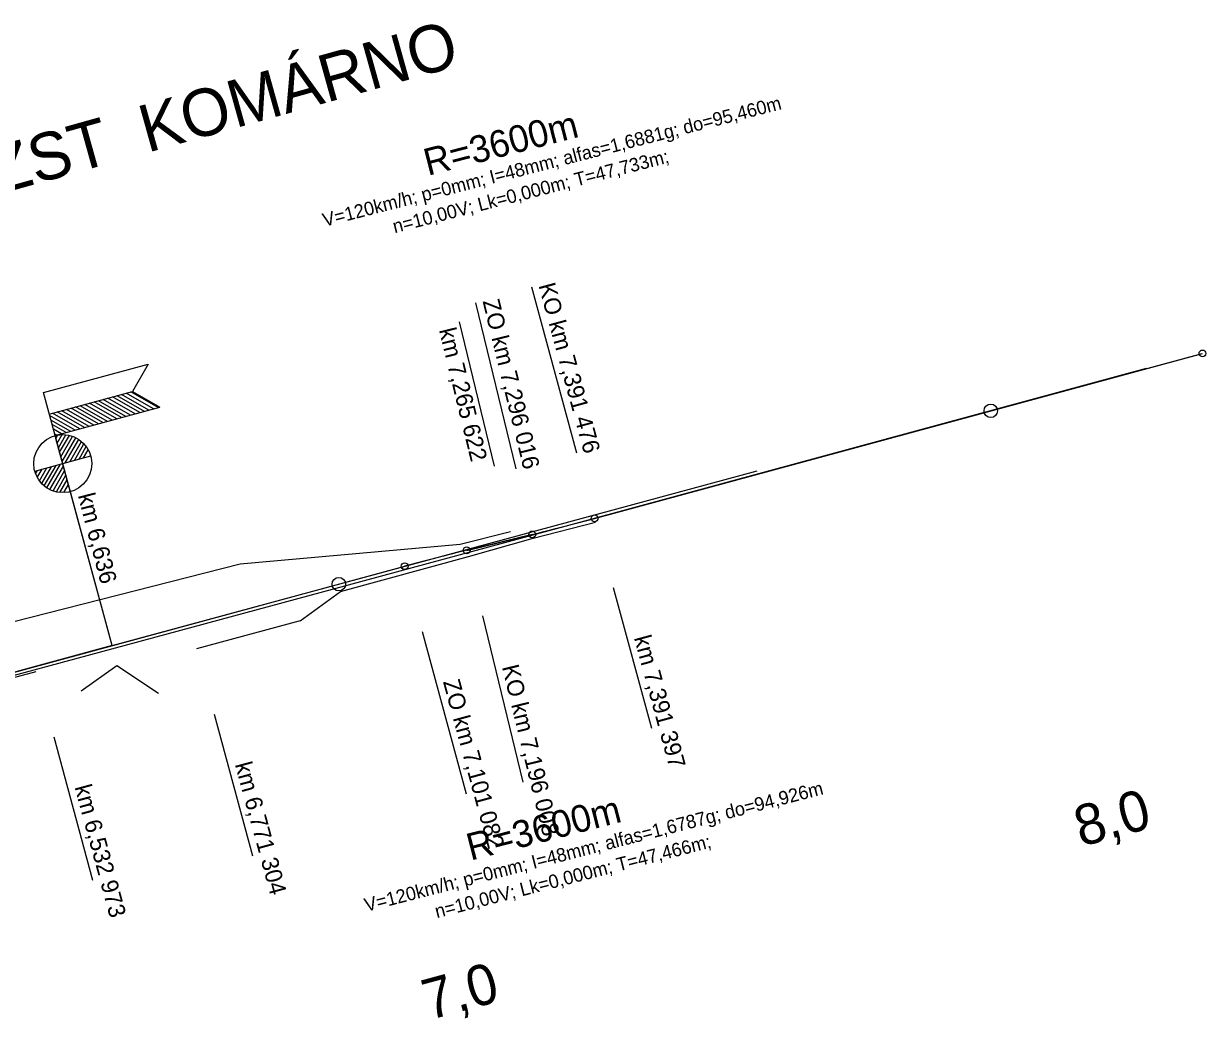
# Model space of a CAD drawing. Extents: x -504999 to -493096, y -1330712 to -1305226.
# Drawn here: x -502082 to -500334, y -1330024 to -1328550 of the extents above; entities that cross this region are included whole.
import ezdxf

# ---------------------------------------------------------------- set-up
doc = ezdxf.new("R2010")
doc.units = 0
for name, color, linetype in [('0_HM', 7, 'Continuous'), ('0_obluky', 7, 'Continuous'), ('0_popis oblukov', 7, 'Continuous'), ('0_STANICE', 7, 'Continuous'), ('0_stanicenie oblukov', 7, 'Continuous'), ('dotyčnice', 7, 'Continuous'), ('Level 1', 7, 'Continuous'), ('PHS', 7, 'Continuous')]:
    doc.layers.add(name, color=color, linetype=linetype)

msp = doc.modelspace()

# ---------------------------------------------------------------- linework, layer by layer
at = {"layer": '0_HM'}
for centre in [(-500648.1, -1329123.6), (-501614.5, -1329380.4)]:
    msp.add_circle(centre, 10, dxfattribs=at)
at = {"layer": '0_obluky'}
for p, q in [((-501235.4, -1329282.9), (-500334.3, -1329038.5)), ((-501327.8, -1329306.7), (-501425, -1329330.3)), ((-501425, -1329330.3), (-501327.8, -1329306.7)), ((-502264, -1329556.4), (-501516.9, -1329353.9))]:
    msp.add_line(p, q, dxfattribs=at)
for centre in [(-500334.3, -1329038.5), (-501235.4, -1329282.9), (-501327.8, -1329306.7), (-501425, -1329330.3), (-501516.9, -1329353.9)]:
    msp.add_circle(centre, 5, dxfattribs=at)
for centre, start, end in [((-502177.8, -1325808.5), 283.6563, 285.1756), ((-500575.1, -1332828.5), 103.6563, 105.1671)]:
    msp.add_arc(centre, 3600, start, end, dxfattribs=at)
at = {"layer": '0_STANICE'}
for p, q in [((-502052.3, -1329096.6), (-501897.3, -1329054.5)), ((-501897.3, -1329054.5), (-501920.5, -1329095)), ((-501950.7, -1329471.5), (-502052.3, -1329096.6)), ((-502043.7, -1329128.4), (-501920.5, -1329095)), ((-501936.9, -1329133.7), (-501977.4, -1329110.4)), ((-501930.1, -1329131.8), (-501970.6, -1329108.6)), ((-501923.3, -1329130), (-501963.8, -1329106.7)), ((-501916.4, -1329128.1), (-501956.9, -1329104.9)), ((-501909.6, -1329126.3), (-501950.1, -1329103)), ((-501902.8, -1329124.4), (-501943.3, -1329101.2)), ((-501896, -1329122.6), (-501936.5, -1329099.3)), ((-501889.1, -1329120.7), (-501929.6, -1329097.5)), ((-501882.3, -1329118.9), (-501922.8, -1329095.6)), ((-501920.5, -1329095), (-501880, -1329118.2)), ((-501998.3, -1329150.3), (-502038.8, -1329127.1)), ((-502035.1, -1329160.3), (-501880, -1329118.2)), ((-501991.5, -1329148.5), (-502032, -1329125.3)), ((-501984.7, -1329146.6), (-502025.2, -1329123.4)), ((-501977.9, -1329144.8), (-502018.4, -1329121.5)), ((-501971, -1329142.9), (-502011.5, -1329119.7)), ((-501964.2, -1329141.1), (-502004.7, -1329117.8)), ((-501957.4, -1329139.2), (-501997.9, -1329116)), ((-501950.6, -1329137.4), (-501991.1, -1329114.1)), ((-501943.7, -1329135.5), (-501984.2, -1329112.3)), ((-502005.2, -1329152.2), (-502043.2, -1329130.4)), ((-502012, -1329154), (-502041.3, -1329137.2)), ((-502018.8, -1329155.9), (-502039.5, -1329144)), ((-502018.8, -1329155.9), (-502039.5, -1329144)), ((-502025.6, -1329157.7), (-502037.6, -1329150.9)), ((-502025.6, -1329157.7), (-502037.6, -1329150.9)), ((-502032.5, -1329159.6), (-502035.8, -1329157.7)), ((-502033.9, -1329164.5), (-502031, -1329159.4)), ((-502032.1, -1329171.3), (-502024.9, -1329158.8)), ((-502030.2, -1329178.2), (-502019.2, -1329159)), ((-502028.4, -1329185), (-502014, -1329159.9)), ((-502026.5, -1329191.8), (-502009.1, -1329161.4)), ((-502024.7, -1329198.6), (-502004.4, -1329163.4)), ((-501950.7, -1329471.5), (-502033.9, -1329164.5)), ((-502020.1, -1329200.8), (-502000.1, -1329165.9)), ((-502013.3, -1329199), (-501996.1, -1329168.9)), ((-502006.5, -1329197.1), (-501992.4, -1329172.4)), ((-501999.7, -1329195.3), (-501989, -1329176.6)), ((-502065.3, -1329213.1), (-501982.3, -1329190.5)), ((-501992.8, -1329193.4), (-501985.9, -1329181.4)), ((-502064, -1329217), (-502061.1, -1329211.9)), ((-502061.5, -1329222.6), (-502054.3, -1329210.1)), ((-502058.4, -1329227.3), (-502047.4, -1329208.2)), ((-502055, -1329231.4), (-502040.6, -1329206.4)), ((-502051.2, -1329234.9), (-502033.8, -1329204.5)), ((-502047.2, -1329237.9), (-502027, -1329202.7)), ((-502042.8, -1329240.4), (-502022.8, -1329205.5)), ((-502038.2, -1329242.3), (-502021, -1329212.3)), ((-502033.3, -1329243.8), (-502019.1, -1329219.1)), ((-502028, -1329244.6), (-502017.3, -1329225.9)), ((-502022.3, -1329244.8), (-502015.4, -1329232.8))]:
    msp.add_line(p, q, dxfattribs=at)
msp.add_circle((-502023.8, -1329201.8), 43, dxfattribs=at)
at = {"layer": '0_stanicenie oblukov'}
for p, q in [((-501261.6, -1329186.4), (-501328.3, -1328940.2)), ((-501351.4, -1329209.5), (-501411.2, -1328963.4)), ((-501401.4, -1329427.5), (-501341.6, -1329673.6)), ((-501490.8, -1329450.4), (-501425.6, -1329690.9)), ((-501950.7, -1329471.5), (-502264.1, -1329556.5))]:
    msp.add_line(p, q, dxfattribs=at)
at = {"layer": 'dotyčnice'}
for p, q in [((-501234.2, -1329282.6), (-500334.5, -1329038.6)), ((-501955.9, -1329472.9), (-500994.3, -1329212.3))]:
    msp.add_line(p, q, dxfattribs=at)
at = {"layer": 'Level 1'}
for points in [[(-500417.5, -1329061.1), (-500981.3, -1329214.1), (-501250.5, -1329287.1), (-501600.6, -1329382.1), (-502121.9, -1329522.8), (-502195.1, -1329542.5)], [(-501996.5, -1329538.6), (-501943.6, -1329501), (-501881.9, -1329542)]]:
    msp.add_lwpolyline(points, dxfattribs=at)
at = {"layer": 'PHS'}
for p, q in [((-501383.6, -1329205.8), (-501435.6, -1328991.7)), ((-501207.7, -1329385.2), (-501151.1, -1329593.9)), ((-501671.8, -1329434.7), (-501825.5, -1329476.3)), ((-502262.4, -1329562.2), (-502063.3, -1329509.9)), ((-501799.3, -1329572.8), (-501742.3, -1329783.1)), ((-502037.1, -1329606.4), (-501979.5, -1329819))]:
    msp.add_line(p, q, dxfattribs=at)
for points in [[(-501360, -1329303), (-501434.7, -1329321.4), (-501760.6, -1329350.8), (-502176.6, -1329456.3), (-502263.1, -1329520.5)], [(-501671.8, -1329434.7), (-501611.9, -1329391.2), (-501422.5, -1329339.2), (-501326.4, -1329312.5), (-501233.9, -1329288.7)]]:
    msp.add_lwpolyline(points, dxfattribs=at)

# ---------------------------------------------------------------- texts
at = {"layer": '0_HM'}
for s, rotation, p in [('8,0', 15.1756, (-500514.5, -1329769.8)), ('7,0', 15.1671, (-501481, -1330026.6))]:
    msp.add_text(s, height=60, rotation=rotation, dxfattribs=at).set_placement(p)
at = {"layer": '0_popis oblukov'}
for s, height, rotation, p in [('V=120km/h; p=0mm; I=48mm; alfas=1,6881g; do=95,460m', 20, 14.416, (-501635.7, -1328851)), ('R=3600m', 40, 14.416, (-501482.6, -1328775.5)), ('n=10,00V; Lk=0,000m; T=47,733m;', 20, 14.416, (-501531.8, -1328860.5)), ('V=120km/h; p=0mm; I=48mm; alfas=1,6787g; do=94,926m', 20, 14.4117, (-501573.7, -1329866)), ('R=3600m', 40, 14.4117, (-501419.2, -1329790.2)), ('n=10,00V; Lk=0,000m; T=47,466m;', 20, 14.4117, (-501469.3, -1329875.4))]:
    msp.add_text(s, height=height, rotation=rotation, dxfattribs=at).set_placement(p)
at = {"layer": '0_STANICE'}
for s, height, rotation, p in [('ŽST  KOMÁRNO', 70, 15.6199, (-502118.8, -1328803)), ('km 6,636', 25, 284.4812, (-502001.5, -1329248.8))]:
    msp.add_text(s, height=height, rotation=rotation, dxfattribs=at).set_placement(p)
at = {"layer": '0_stanicenie oblukov'}
for s, rotation, p in [('KO km 7,391 476', 285.1756, (-501318.7, -1328937.6)), ('ZO km 7,296 016', 283.6563, (-501401.5, -1328961.1)), ('KO km 7,196 008', 283.6563, (-501372.8, -1329502.8)), ('ZO km 7,101 082', 285.1671, (-501460.2, -1329525))]:
    msp.add_text(s, height=25, rotation=rotation, dxfattribs=at).set_placement(p)
at = {"layer": 'PHS'}
for s, rotation, p in [('km 7,265 622', 283.6563, (-501466.2, -1329003.7)), ('km 7,391 397', 285.1744, (-501177.1, -1329459.8)), ('km 6,771 304', 285.1671, (-501768.7, -1329647.4)), ('km 6,532 973', 285.1671, (-502006.5, -1329681))]:
    msp.add_text(s, height=25, rotation=rotation, dxfattribs=at).set_placement(p)

doc.saveas('drawing.dxf')
